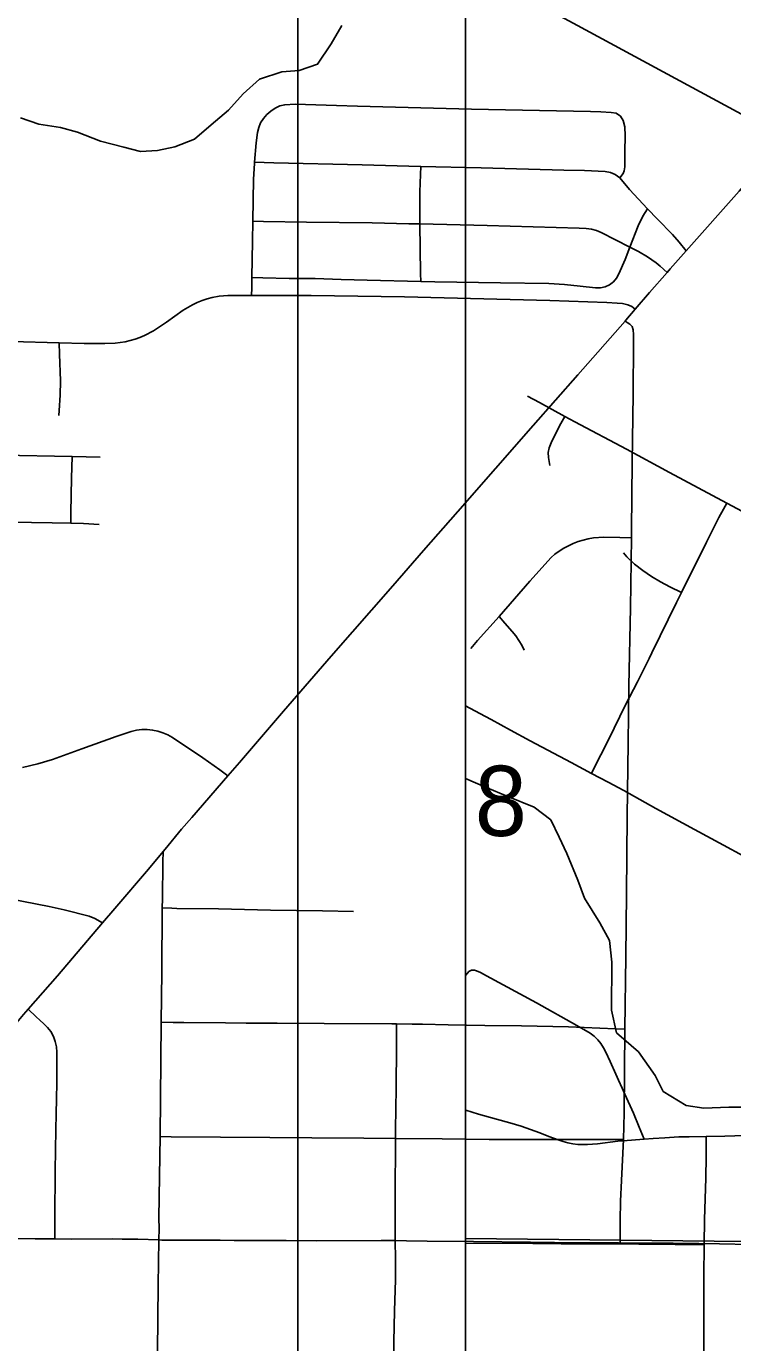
# Model space of a CAD drawing. Extents: x 0 to 34, y 0 to 22.
# Drawn here: x 12.978 to 13.4, y 18.187 to 18.972 of the extents above; entities that cross this region are included whole.
import ezdxf

# ---------------------------------------------------------------- set-up
doc = ezdxf.new("R2010")
doc.units = 0
for name, color, linetype in [('GM_X_City_Street', 7, 'Continuous'), ('GM_X_Corporation', 7, 'Continuous'), ('GM_X_Minor_River', 7, 'Continuous'), ('GM_X_Rail_Line', 7, 'Continuous'), ('GM_X_Section_Text', 7, 'Continuous'), ('GM_X_State_Route', 7, 'Continuous'), ('GM_X_US_Shield', 7, 'Continuous'), ('SH_Data', 7, 'Continuous')]:
    doc.layers.add(name, color=color, linetype=linetype)

msp = doc.modelspace()

# ---------------------------------------------------------------- linework, layer by layer
at = {"layer": 'GM_X_City_Street'}
for p, q in [((13.00568, 18.71562), (13.02233, 18.71536)), ((13.05804, 18.30972), (13.05876, 18.378))]:
    msp.add_line(p, q, dxfattribs=at)
for points in [[(13.11444, 18.89135), (13.1155, 18.90288), (13.11626, 18.90904), (13.11697, 18.91205), (13.11813, 18.91491), (13.1198, 18.91751), (13.12186, 18.91982), (13.12419, 18.92187), (13.12675, 18.92361), (13.12954, 18.92494), (13.13253, 18.92566), (13.13872, 18.92589), (13.16348, 18.92517), (13.17586, 18.92474), (13.24396, 18.923), (13.31515, 18.92156), (13.32133, 18.92135), (13.32742, 18.921), (13.33046, 18.92062), (13.33299, 18.91892), (13.33451, 18.91626), (13.33551, 18.91236), (13.33569, 18.90707), (13.33566, 18.89781), (13.33563, 18.88852), (13.33521, 18.88612), (13.33456, 18.88459), (13.33262, 18.88192)], [(13.11352, 18.85605), (13.11395, 18.8813), (13.11436, 18.89058), (13.11444, 18.89135)], [(13.11444, 18.89135), (13.12607, 18.89105), (13.17877, 18.88971), (13.20656, 18.88898), (13.21387, 18.8888)], [(13.21323, 18.85446), (13.21309, 18.86435), (13.21314, 18.87371), (13.21363, 18.88407), (13.21387, 18.8888)], [(13.21387, 18.8888), (13.24981, 18.88792), (13.29914, 18.88666), (13.3115, 18.88633), (13.32389, 18.8857), (13.32693, 18.88518), (13.32974, 18.88396), (13.33262, 18.88192)], [(13.37219, 18.83847), (13.40375, 18.87411), (13.42185, 18.89499)], [(13.33262, 18.88192), (13.3383, 18.87505), (13.3491, 18.8635)], [(13.33856, 18.84063), (13.34354, 18.85334), (13.34629, 18.85916), (13.3491, 18.8635)], [(13.3491, 18.8635), (13.35504, 18.85744), (13.36404, 18.84829), (13.3681, 18.84366), (13.37219, 18.83847)], [(13.11291, 18.82252), (13.11332, 18.84416), (13.11352, 18.85605)], [(13.11352, 18.85605), (13.11981, 18.85597), (13.14547, 18.85561), (13.18478, 18.85507), (13.20652, 18.85462), (13.21323, 18.85446)], [(13.21323, 18.85446), (13.25335, 18.85353), (13.30827, 18.852), (13.31256, 18.8517), (13.31567, 18.85136), (13.31866, 18.85056), (13.32154, 18.84937), (13.33856, 18.84063)], [(13.21369, 18.82022), (13.21363, 18.82487), (13.21323, 18.85446)], [(13.21369, 18.82022), (13.22218, 18.82003), (13.26128, 18.81937), (13.29019, 18.81889), (13.29948, 18.81838), (13.30883, 18.8174), (13.31805, 18.81632), (13.32104, 18.81636), (13.32389, 18.81691), (13.32652, 18.81807), (13.3288, 18.81984), (13.33064, 18.82209), (13.33209, 18.82469), (13.3357, 18.83333), (13.33856, 18.84063)], [(13.33856, 18.84063), (13.34371, 18.83798), (13.34913, 18.83492), (13.35424, 18.83133), (13.35668, 18.82938), (13.36077, 18.82556)], [(13.36077, 18.82556), (13.36259, 18.82762), (13.37219, 18.83847)], [(13.34175, 18.80355), (13.35033, 18.81363), (13.36077, 18.82556)], [(13.11271, 18.81175), (13.11279, 18.8163), (13.11291, 18.82252)], [(13.11291, 18.82252), (13.11953, 18.82236), (13.13506, 18.82196), (13.15064, 18.82186), (13.16622, 18.82142), (13.18178, 18.82095), (13.21369, 18.82022)], [(12.96942, 18.78434), (12.99792, 18.78357), (13.01276, 18.78317), (13.02511, 18.78304), (13.03123, 18.78335), (13.03727, 18.7842), (13.04318, 18.78566), (13.04604, 18.78665), (13.04883, 18.78783), (13.05418, 18.79073), (13.06185, 18.79585), (13.07195, 18.80309), (13.07739, 18.80627), (13.08024, 18.80762), (13.08317, 18.80879), (13.08616, 18.80978), (13.08922, 18.81059), (13.09335, 18.81132), (13.0986, 18.81177), (13.11271, 18.81175), (13.14822, 18.8117), (13.204, 18.81093), (13.29074, 18.80883), (13.32484, 18.80768), (13.33106, 18.80729), (13.33416, 18.80691), (13.33738, 18.80619), (13.33983, 18.80512), (13.34175, 18.80355)], [(13.33578, 18.79656), (13.33623, 18.79707), (13.34175, 18.80355)], [(13.09862, 18.5251), (13.10546, 18.533), (13.13175, 18.56362), (13.1602, 18.59646), (13.19698, 18.63852), (13.21542, 18.65949), (13.23591, 18.68281), (13.28092, 18.7341), (13.30755, 18.76441), (13.33578, 18.79656)], [(13.33948, 18.66723), (13.33955, 18.6719), (13.33998, 18.71229), (13.3405, 18.75266), (13.34067, 18.78371), (13.34074, 18.7885), (13.34054, 18.7913), (13.33994, 18.7932), (13.33864, 18.7946), (13.33704, 18.7957), (13.33578, 18.79656)], [(12.99756, 18.74006), (12.99789, 18.7431), (12.99851, 18.75223), (12.99855, 18.7608), (12.99805, 18.77683), (12.99792, 18.78357)], [(13.27752, 18.75176), (13.28461, 18.74793), (13.29971, 18.73963), (13.30582, 18.73628), (13.3366, 18.72011), (13.36224, 18.70623), (13.39649, 18.68778), (13.40574, 18.68287)], [(13.2907, 18.71028), (13.28998, 18.71516), (13.28988, 18.71808), (13.29044, 18.72095), (13.29196, 18.72487), (13.29745, 18.73533), (13.29971, 18.73963)], [(12.87934, 18.71844), (12.87943, 18.71128), (12.87973, 18.68935), (12.87993, 18.68624), (12.88068, 18.68326), (12.88233, 18.68068), (12.88487, 18.67902), (12.88792, 18.67847), (12.94389, 18.67695), (12.99365, 18.67607), (13.0047, 18.67581)], [(12.9449, 18.71698), (12.96359, 18.71656), (13.00568, 18.71562)], [(13.0047, 18.67581), (13.00481, 18.68198), (13.00519, 18.70303), (13.00543, 18.70905), (13.00568, 18.71562)], [(13.31568, 18.52653), (13.31875, 18.53255), (13.32375, 18.54252), (13.32928, 18.55361), (13.33603, 18.56749), (13.34305, 18.58128), (13.3501, 18.59505), (13.3518, 18.59852), (13.36648, 18.62847), (13.36943, 18.63442), (13.38437, 18.66458), (13.39175, 18.67918), (13.3945, 18.68427), (13.39649, 18.68778)], [(13.0047, 18.67581), (13.01231, 18.67563), (13.02163, 18.67515)], [(13.24353, 18.60118), (13.24765, 18.60593), (13.26045, 18.62026), (13.2789, 18.64133), (13.29152, 18.65536), (13.29388, 18.65744), (13.29644, 18.65926), (13.29912, 18.66091), (13.30472, 18.66379), (13.30765, 18.66491), (13.31374, 18.66652), (13.31684, 18.66705), (13.32312, 18.66749), (13.33256, 18.66734), (13.33948, 18.66723)], [(13.33558, 18.37394), (13.3362, 18.41715), (13.33656, 18.45445), (13.33706, 18.50104), (13.3376, 18.54454), (13.33804, 18.57872), (13.33892, 18.62531), (13.33948, 18.66723)], [(13.33482, 18.65818), (13.33676, 18.65572), (13.34135, 18.65148), (13.34632, 18.64761), (13.35149, 18.644), (13.35692, 18.64079), (13.36253, 18.63793), (13.36943, 18.63442)], [(13.27548, 18.6001), (13.27402, 18.60309), (13.27235, 18.60594), (13.27044, 18.60866), (13.26838, 18.61125), (13.26399, 18.61623), (13.26045, 18.62026)], [(12.97603, 18.53002), (12.98504, 18.53216), (12.9939, 18.53488), (13.01143, 18.54118), (13.03194, 18.54859), (13.04085, 18.55158), (13.04397, 18.55228), (13.04716, 18.55267), (13.05037, 18.55272), (13.05356, 18.55243), (13.05671, 18.55179), (13.05977, 18.5508), (13.06269, 18.54948), (13.06546, 18.54789), (13.08361, 18.53577), (13.09384, 18.52867), (13.09862, 18.5251)], [(13.05992, 18.47993), (13.06106, 18.48128), (13.07093, 18.49315), (13.07697, 18.50018), (13.09862, 18.5251)], [(13.02379, 18.43726), (13.0311, 18.44583), (13.05112, 18.46944), (13.05992, 18.47993)], [(13.05941, 18.44625), (13.05946, 18.45167), (13.05981, 18.47354), (13.05992, 18.47993)], [(12.8584, 18.44972), (12.8612, 18.45209), (12.86407, 18.45335), (12.86637, 18.45385), (12.86862, 18.45412), (12.87461, 18.45431), (12.88384, 18.45432), (12.90566, 18.45411), (12.93054, 18.45378), (12.94293, 18.45392), (12.95219, 18.45385), (12.95832, 18.45339), (12.9644, 18.45254), (12.97655, 18.44999), (12.99176, 18.44707), (13.00074, 18.44502), (13.01576, 18.44125), (13.01903, 18.43988), (13.02379, 18.43726)], [(13.05876, 18.378), (13.05908, 18.40792), (13.05941, 18.44625)], [(13.05941, 18.44625), (13.06503, 18.44608), (13.06814, 18.44599), (13.09297, 18.44572), (13.12399, 18.44499), (13.15504, 18.44451), (13.17359, 18.44407)], [(12.97933, 18.38574), (12.99691, 18.40578), (13.02379, 18.43726)], [(13.2404, 18.40579), (13.24048, 18.40589), (13.24159, 18.40723), (13.24252, 18.40824), (13.24323, 18.40876), (13.24406, 18.40911), (13.24505, 18.40911)], [(13.34716, 18.3083), (13.34421, 18.3154), (13.34072, 18.32381), (13.33567, 18.33503), (13.33407, 18.33869), (13.33186, 18.34337), (13.33021, 18.34709), (13.32691, 18.35461), (13.3243, 18.36012), (13.3229, 18.36279), (13.32132, 18.3653), (13.31946, 18.36759), (13.3173, 18.36961), (13.31492, 18.37141), (13.30701, 18.37605), (13.28275, 18.38951), (13.25294, 18.4057), (13.24948, 18.4076), (13.24695, 18.40876), (13.2459, 18.40901), (13.24505, 18.40911)], [(12.91958, 18.32284), (12.93208, 18.33551), (12.9467, 18.34997), (12.95706, 18.36032), (12.96479, 18.36841), (12.97076, 18.37551), (12.97263, 18.37786), (12.97652, 18.38254), (12.97933, 18.38574)], [(12.99514, 18.24866), (12.99514, 18.25094), (12.99514, 18.26149), (12.99546, 18.28924), (12.99587, 18.31398), (12.99605, 18.3232), (12.99624, 18.33241), (12.99641, 18.34167), (12.9964, 18.34783), (12.99646, 18.36022), (12.99616, 18.3634), (12.99547, 18.36652), (12.99438, 18.36955), (12.99284, 18.37239), (12.99083, 18.37491), (12.98857, 18.37711), (12.98636, 18.37921), (12.98414, 18.38128), (12.97933, 18.38574)], [(13.05876, 18.378), (13.06599, 18.37793), (13.07218, 18.37786), (13.09709, 18.37757), (13.10952, 18.37749), (13.11878, 18.37749), (13.12807, 18.37743), (13.15607, 18.3772), (13.19636, 18.37703), (13.19916, 18.37701), (13.20855, 18.37694), (13.21471, 18.37681), (13.23019, 18.37649), (13.252, 18.37614), (13.27383, 18.37583), (13.3019, 18.37518), (13.32995, 18.37414), (13.33558, 18.37394)], [(13.19773, 18.15004), (13.1975, 18.1625), (13.1976, 18.18027), (13.19764, 18.18716), (13.19797, 18.20569), (13.19867, 18.22426), (13.19866, 18.23663), (13.19845, 18.24764), (13.19843, 18.24898), (13.19842, 18.27359), (13.19866, 18.30863), (13.19869, 18.31391), (13.19913, 18.33873), (13.19932, 18.36354), (13.19921, 18.37284), (13.19916, 18.37701)], [(13.33471, 18.308), (13.3351, 18.32395), (13.33558, 18.37394)], [(13.2404, 18.32551), (13.24057, 18.32546), (13.2482, 18.32315), (13.25903, 18.32013), (13.26701, 18.31801), (13.27378, 18.31597), (13.27656, 18.31501), (13.27933, 18.31401), (13.28482, 18.31196), (13.29028, 18.30986), (13.29586, 18.30782), (13.29871, 18.30687), (13.30162, 18.30603), (13.30455, 18.30542), (13.30743, 18.30511), (13.31324, 18.30507), (13.31922, 18.30552), (13.33132, 18.30709), (13.33439, 18.30729), (13.34716, 18.3083), (13.35248, 18.30859), (13.3595, 18.30895), (13.36785, 18.30952), (13.37399, 18.30964), (13.3842, 18.30977)], [(13.05733, 18.24805), (13.05746, 18.25483), (13.0574, 18.26106), (13.05778, 18.28604), (13.05804, 18.30972)], [(13.05804, 18.30972), (13.06477, 18.30967), (13.12371, 18.30925), (13.1486, 18.30909), (13.17977, 18.30881), (13.19866, 18.30863), (13.22652, 18.30836), (13.25454, 18.30807), (13.26077, 18.30808), (13.27733, 18.30802), (13.29816, 18.30794), (13.32621, 18.30794), (13.32933, 18.30796), (13.33471, 18.308)], [(13.33285, 18.24623), (13.33285, 18.24874), (13.33285, 18.25961), (13.33306, 18.27119), (13.33349, 18.28364), (13.33471, 18.308)], [(13.38178, 18.00782), (13.38178, 18.01587), (13.38177, 18.02323), (13.38177, 18.03117), (13.382, 18.05901), (13.38234, 18.0767), (13.38259, 18.08996), (13.3826, 18.10839), (13.38259, 18.12262), (13.38266, 18.12838), (13.38272, 18.13434), (13.3828, 18.15537), (13.38277, 18.16152), (13.38278, 18.17635), (13.3828, 18.18918), (13.3827, 18.20464), (13.3828, 18.2263), (13.38297, 18.24526), (13.38323, 18.26024), (13.38397, 18.28487), (13.38416, 18.29779), (13.3842, 18.30977)], [(13.41314, 18.31056), (13.39532, 18.30995), (13.3842, 18.30977)], [(12.91869, 18.24938), (12.92494, 18.24948), (12.92818, 18.24952), (12.94042, 18.24936), (12.95882, 18.24909), (12.98342, 18.24873), (12.99514, 18.24866)], [(12.99514, 18.24866), (13.00498, 18.24861), (13.02941, 18.24866), (13.03539, 18.24861), (13.04487, 18.24848), (13.05733, 18.24805)], [(13.05651, 18.18141), (13.05684, 18.22113), (13.05733, 18.24805)], [(13.05733, 18.24805), (13.05915, 18.24799), (13.09388, 18.24786), (13.10225, 18.24774), (13.11283, 18.24774), (13.12121, 18.24774), (13.13328, 18.24774), (13.15137, 18.24749), (13.19001, 18.24768), (13.19845, 18.24764)], [(13.19845, 18.24764), (13.20523, 18.2476), (13.2175, 18.24736), (13.24527, 18.24713), (13.27917, 18.24676), (13.29358, 18.24662), (13.33175, 18.24625), (13.33285, 18.24623)], [(13.2404, 18.24603), (13.2636, 18.24605), (13.29761, 18.24579), (13.3136, 18.24584), (13.32673, 18.24566), (13.34397, 18.2455), (13.3656, 18.24543), (13.37978, 18.24529), (13.38297, 18.24526)], [(13.33285, 18.24623), (13.34173, 18.24612), (13.35525, 18.2461), (13.36441, 18.24616), (13.37979, 18.24597), (13.39216, 18.24579), (13.41069, 18.24535), (13.43236, 18.24523), (13.45512, 18.245), (13.47072, 18.2447)]]:
    msp.add_lwpolyline(points, dxfattribs=at)
at = {"layer": 'GM_X_Corporation'}
msp.add_lwpolyline([(13.2404, 19.74462), (13.2404, 15.59448)], dxfattribs=at)
at = {"layer": 'GM_X_Minor_River'}
for points in [[(13.16665, 18.97288), (13.16014, 18.9619), (13.15211, 18.94979), (13.14108, 18.94606), (13.13084, 18.94536), (13.11753, 18.94089), (13.10762, 18.93221), (13.09884, 18.92239), (13.08855, 18.91371), (13.07864, 18.90503), (13.06685, 18.90055), (13.05659, 18.89833), (13.04634, 18.89764), (13.03649, 18.90036), (13.02247, 18.90387), (13.00884, 18.90928), (12.9986, 18.91201), (12.98572, 18.91399), (12.97473, 18.91786)], [(13.2404, 18.5234), (13.2524, 18.51826), (13.26574, 18.51265), (13.28137, 18.5063), (13.29131, 18.49877), (13.29633, 18.48855), (13.30098, 18.4787), (13.30757, 18.46278), (13.31145, 18.45216), (13.32069, 18.43741), (13.32648, 18.42681)], [(13.32648, 18.42681), (13.32772, 18.41389)], [(13.32772, 18.41389), (13.32768, 18.38526), (13.33057, 18.37175), (13.34382, 18.3603), (13.35364, 18.34619), (13.35854, 18.33667), (13.37218, 18.32825), (13.3828, 18.32668), (13.39761, 18.32738), (13.40748, 18.32733)]]:
    msp.add_lwpolyline(points, dxfattribs=at)
at = {"layer": 'GM_X_Rail_Line'}
for points in [[(13.2404, 20.24939), (13.2404, 14.2201)], [(13.2404, 19.00908), (13.30728, 18.97287), (13.38065, 18.93337), (13.59279, 18.8187), (13.68154, 18.77009), (13.71117, 18.75124), (13.74654, 18.72472), (13.76773, 18.70622), (13.78466, 18.69019), (13.80236, 18.67223), (13.81891, 18.65351), (13.8334, 18.63581), (13.88555, 18.57297), (14.04503, 18.37569), (14.08659, 18.32516), (14.10031, 18.30951)]]:
    msp.add_lwpolyline(points, dxfattribs=at)
at = {"layer": 'GM_X_State_Route'}
msp.add_lwpolyline([(13.2404, 18.56693), (13.24908, 18.56225), (13.25576, 18.55864), (13.26727, 18.55235), (13.27903, 18.54606), (13.30351, 18.53295), (13.31568, 18.52653), (13.32558, 18.52132), (13.33494, 18.51624), (13.35407, 18.50567), (13.3772, 18.49296), (13.39445, 18.4836), (13.40622, 18.47731)], dxfattribs=at)
at = {"layer": 'GM_X_US_Shield'}
for points in [[(13.2404, 19.25055), (13.2404, 18.2489), (14.09372, 18.2398), (14.10087, 19.24199)], [(13.2404, 18.2489), (13.2404, 17.23459), (14.08752, 17.22638), (14.09372, 18.2398)]]:
    msp.add_lwpolyline(points, close=True, dxfattribs=at)
at = {"layer": 'SH_Data'}
for p, q in [((13.1404, 21), (13.1404, 14)), ((13.2404, 20.9), (13.2404, 14.1))]:
    msp.add_line(p, q, dxfattribs=at)

# ---------------------------------------------------------------- texts
at = {"layer": 'GM_X_Section_Text'}
msp.add_text('8', height=0.04186, rotation=0.00001, dxfattribs=at).set_placement((13.24597, 18.48921))

doc.saveas('drawing.dxf')
